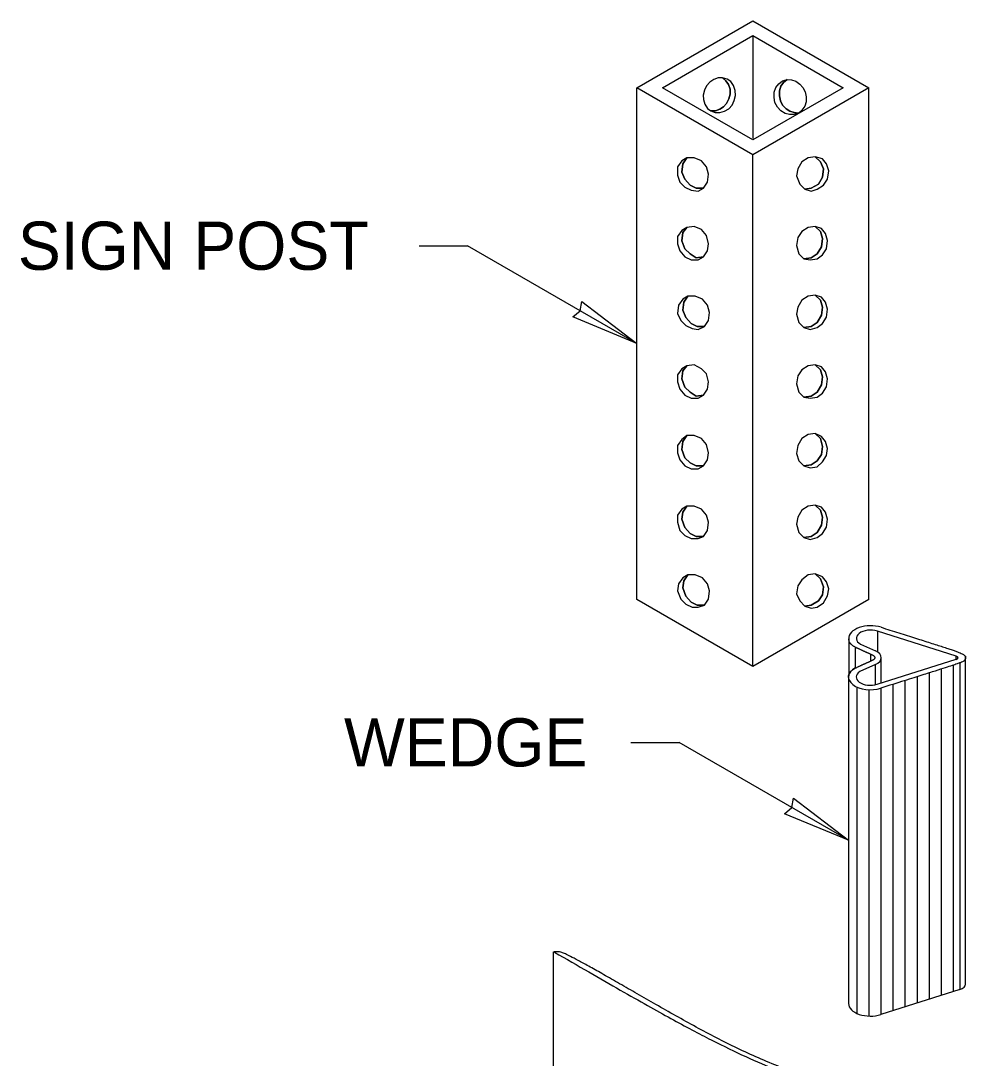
# Model space of a CAD drawing. Extents: x 99862 to 103680, y 99470 to 102076.
# Drawn here: x 101247.5 to 101566.5, y 100505.2 to 100849.7 of the extents above; entities that cross this region are included whole.
import ezdxf

# ---------------------------------------------------------------- set-up
doc = ezdxf.new("R2010")
doc.units = 0
for name, color, linetype in [('Level 15', 7, 'Continuous'), ('Level 2', 7, 'Continuous'), ('Level 20', 7, 'Continuous'), ('Level 4', 7, 'Continuous'), ('Level 8', 7, 'Continuous')]:
    doc.layers.add(name, color=color, linetype=linetype)

msp = doc.modelspace()

# ---------------------------------------------------------------- linework, layer by layer
at = {"layer": 'Level 15'}
for p, q in [((101379.81, 100775.01), (101395.81, 100775.01)), ((101452.1, 100742.51), (101395.81, 100775.01)), ((101450.1, 100610.06), (101466.1, 100610.06)), ((101522.39, 100577.56), (101466.1, 100610.06))]:
    msp.add_line(p, q, dxfattribs=at)
for points in [[(101452.1, 100742.51), (101430.84, 100751.34), (101433.24, 100753.39), (101433.82, 100756.51)], [(101522.39, 100577.56), (101501.13, 100586.39), (101503.54, 100588.45), (101504.11, 100591.56)]]:
    msp.add_lwpolyline(points, close=True, dxfattribs=at)
at = {"layer": 'Level 2'}
for p, q in [((101452.1, 100827.48), (101490.62, 100849.72)), ((101490.62, 100849.72), (101529.13, 100827.48)), ((101460.66, 100827.48), (101490.62, 100844.77)), ((101490.56, 100844.79), (101490.56, 100810.62)), ((101490.62, 100844.77), (101520.58, 100827.48)), ((101452.1, 100657.54), (101452.1, 100827.48)), ((101490.62, 100805.24), (101452.1, 100827.48)), ((101490.62, 100810.18), (101460.66, 100827.48)), ((101529.13, 100827.48), (101490.62, 100805.24)), ((101520.58, 100827.48), (101490.62, 100810.18)), ((101529.13, 100657.54), (101529.13, 100827.48)), ((101466.99, 100803.16), (101465.62, 100801.15)), ((101468.71, 100804.17), (101466.99, 100803.16)), ((101468.71, 100804.17), (101467.34, 100802.15)), ((101467.34, 100802.15), (101468.71, 100804.17)), ((101471.11, 100804.17), (101468.71, 100804.17)), ((101473.51, 100803.16), (101471.11, 100804.17)), ((101475.23, 100801.15), (101473.51, 100803.16)), ((101490.62, 100635.3), (101490.62, 100805.24)), ((101508.93, 100804.19), (101506.87, 100802.85)), ((101511.33, 100804.52), (101508.93, 100804.19)), ((101513.05, 100802.85), (101511.33, 100804.52)), ((101511.33, 100804.52), (101513.05, 100802.85)), ((101513.74, 100803.85), (101511.33, 100804.52)), ((101515.11, 100802.18), (101513.74, 100803.85)), ((101465.62, 100801.15), (101465.62, 100798.47)), ((101467.34, 100802.15), (101466.99, 100799.47)), ((101466.99, 100799.47), (101467.34, 100802.15)), ((101475.91, 100798.8), (101475.23, 100801.15)), ((101505.5, 100800.5), (101505.16, 100798.16)), ((101506.87, 100802.85), (101505.5, 100800.5)), ((101514.08, 100800.5), (101513.05, 100802.85)), ((101513.05, 100802.85), (101514.08, 100800.5)), ((101513.74, 100797.82), (101514.08, 100800.5)), ((101514.08, 100800.5), (101513.74, 100797.82)), ((101515.79, 100799.83), (101515.11, 100802.18)), ((101515.45, 100797.15), (101515.79, 100799.83)), ((101465.62, 100798.47), (101466.31, 100796.12)), ((101466.31, 100796.12), (101468.02, 100794.44)), ((101466.99, 100799.47), (101468.02, 100797.13)), ((101468.02, 100797.13), (101466.99, 100799.47)), ((101468.02, 100797.13), (101469.74, 100795.12)), ((101469.74, 100795.12), (101468.02, 100797.13)), ((101474.2, 100794.11), (101475.57, 100796.12)), ((101475.57, 100796.12), (101475.91, 100798.8)), ((101505.16, 100798.16), (101506.19, 100795.47)), ((101512.36, 100795.47), (101513.74, 100797.82)), ((101513.74, 100797.82), (101512.36, 100795.47)), ((101514.08, 100795.14), (101515.45, 100797.15)), ((101468.02, 100794.44), (101470.08, 100793.44)), ((101469.74, 100795.12), (101471.8, 100794.11)), ((101471.8, 100794.11), (101469.74, 100795.12)), ((101470.08, 100793.44), (101472.48, 100793.1)), ((101471.8, 100794.11), (101474.2, 100794.11)), ((101474.2, 100794.11), (101471.8, 100794.11)), ((101472.48, 100793.1), (101474.2, 100794.11)), ((101506.19, 100795.47), (101507.9, 100793.8)), ((101507.9, 100793.8), (101509.96, 100794.13)), ((101509.96, 100794.13), (101507.9, 100793.8)), ((101507.9, 100793.8), (101509.96, 100793.13)), ((101509.96, 100794.13), (101512.36, 100795.47)), ((101512.36, 100795.47), (101509.96, 100794.13)), ((101509.96, 100793.13), (101512.02, 100793.8)), ((101512.02, 100793.8), (101514.08, 100795.14)), ((101466.99, 100780.03), (101465.62, 100778.02)), ((101468.71, 100781.04), (101466.99, 100780.03)), ((101467.34, 100779.36), (101466.99, 100776.68)), ((101466.99, 100776.68), (101467.34, 100779.36)), ((101468.71, 100781.04), (101467.34, 100779.36)), ((101467.34, 100779.36), (101468.71, 100781.04)), ((101471.11, 100781.37), (101468.71, 100781.04)), ((101473.51, 100780.37), (101471.11, 100781.37)), ((101475.23, 100778.35), (101473.51, 100780.37)), ((101506.87, 100779.72), (101505.5, 100777.71)), ((101508.93, 100781.06), (101506.87, 100779.72)), ((101511.33, 100781.39), (101508.93, 100781.06)), ((101513.05, 100779.72), (101511.33, 100781.39)), ((101513.39, 100780.72), (101511.33, 100781.39)), ((101511.33, 100781.39), (101513.05, 100779.72)), ((101513.74, 100777.37), (101513.05, 100779.72)), ((101513.05, 100779.72), (101513.74, 100777.37)), ((101514.76, 100779.05), (101513.39, 100780.72)), ((101515.45, 100776.7), (101514.76, 100779.05)), ((101465.62, 100778.02), (101465.62, 100775.67)), ((101465.62, 100775.67), (101466.31, 100773.33)), ((101466.99, 100776.68), (101468.02, 100774)), ((101468.02, 100774), (101466.99, 100776.68)), ((101475.91, 100775.67), (101475.23, 100778.35)), ((101475.57, 100773.33), (101475.91, 100775.67)), ((101505.5, 100777.71), (101505.16, 100775.03)), ((101513.39, 100774.69), (101513.74, 100777.37)), ((101513.74, 100777.37), (101513.39, 100774.69)), ((101515.11, 100774.02), (101515.45, 100776.7)), ((101466.31, 100773.33), (101468.02, 100771.32)), ((101468.02, 100774), (101469.74, 100772.32)), ((101469.74, 100772.32), (101468.02, 100774)), ((101469.74, 100772.32), (101471.8, 100770.98)), ((101471.8, 100770.98), (101469.74, 100772.32)), ((101474.2, 100771.32), (101475.57, 100773.33)), ((101505.16, 100775.03), (101505.85, 100772.34)), ((101505.85, 100772.34), (101507.56, 100770.67)), ((101509.96, 100771), (101512.02, 100772.34)), ((101512.02, 100772.34), (101509.96, 100771)), ((101512.02, 100772.34), (101513.39, 100774.69)), ((101513.39, 100774.69), (101512.02, 100772.34)), ((101512.02, 100770.67), (101513.74, 100772.01)), ((101513.74, 100772.01), (101515.11, 100774.02)), ((101468.02, 100771.32), (101470.08, 100770.31)), ((101470.08, 100770.31), (101472.48, 100770.31)), ((101471.8, 100770.98), (101474.2, 100771.32)), ((101474.2, 100771.32), (101471.8, 100770.98)), ((101472.48, 100770.31), (101474.2, 100771.32)), ((101507.56, 100770.67), (101509.96, 100771)), ((101509.96, 100771), (101507.56, 100770.67)), ((101507.56, 100770.67), (101509.62, 100770.33)), ((101509.62, 100770.33), (101512.02, 100770.67)), ((101469.05, 100758.24), (101467.34, 100757.24)), ((101469.05, 100758.24), (101467.68, 100756.23)), ((101467.68, 100756.23), (101469.05, 100758.24)), ((101471.45, 100758.24), (101469.05, 100758.24)), ((101473.85, 100757.24), (101471.45, 100758.24)), ((101508.93, 100758.26), (101506.87, 100756.92)), ((101511.33, 100758.6), (101508.93, 100758.26)), ((101513.05, 100756.92), (101511.33, 100758.6)), ((101513.39, 100757.93), (101511.33, 100758.6)), ((101511.33, 100758.6), (101513.05, 100756.92)), ((101465.96, 100755.22), (101465.62, 100752.54)), ((101467.34, 100757.24), (101465.96, 100755.22)), ((101467.68, 100756.23), (101467.34, 100753.55)), ((101467.34, 100753.55), (101467.68, 100756.23)), ((101475.57, 100755.22), (101473.85, 100757.24)), ((101476.26, 100752.88), (101475.57, 100755.22)), ((101506.87, 100756.92), (101505.5, 100754.58)), ((101513.74, 100754.58), (101513.05, 100756.92)), ((101513.05, 100756.92), (101513.74, 100754.58)), ((101514.76, 100756.25), (101513.39, 100757.93)), ((101515.45, 100753.91), (101514.76, 100756.25)), ((101465.62, 100752.54), (101466.65, 100750.2)), ((101467.34, 100753.55), (101468.37, 100751.2)), ((101468.37, 100751.2), (101467.34, 100753.55)), ((101475.91, 100750.2), (101476.26, 100752.88)), ((101505.5, 100754.58), (101505.16, 100752.23)), ((101505.16, 100752.23), (101505.85, 100749.55)), ((101512.02, 100749.55), (101513.39, 100751.9)), ((101513.39, 100751.9), (101512.02, 100749.55)), ((101513.39, 100751.9), (101513.74, 100754.58)), ((101513.74, 100754.58), (101513.39, 100751.9)), ((101515.11, 100751.23), (101515.45, 100753.91)), ((101466.65, 100750.2), (101468.37, 100748.52)), ((101468.37, 100751.2), (101470.08, 100749.19)), ((101470.08, 100749.19), (101468.37, 100751.2)), ((101468.37, 100748.52), (101470.42, 100747.51)), ((101470.08, 100749.19), (101472.14, 100748.19)), ((101472.14, 100748.19), (101470.08, 100749.19)), ((101472.14, 100748.19), (101474.54, 100748.19)), ((101474.54, 100748.19), (101472.14, 100748.19)), ((101472.48, 100747.18), (101474.54, 100748.19)), ((101474.54, 100748.19), (101475.91, 100750.2)), ((101505.85, 100749.55), (101507.56, 100747.87)), ((101507.56, 100747.87), (101509.96, 100748.21)), ((101509.96, 100748.21), (101507.56, 100747.87)), ((101507.56, 100747.87), (101509.62, 100747.2)), ((101509.62, 100747.2), (101512.02, 100747.87)), ((101509.96, 100748.21), (101512.02, 100749.55)), ((101512.02, 100749.55), (101509.96, 100748.21)), ((101512.02, 100747.87), (101513.74, 100749.21)), ((101513.74, 100749.21), (101515.11, 100751.23)), ((101470.42, 100747.51), (101472.48, 100747.18)), ((101466.99, 100734.11), (101465.62, 100732.1)), ((101468.71, 100735.11), (101466.99, 100734.11)), ((101468.71, 100735.11), (101467.34, 100733.44)), ((101467.34, 100733.44), (101468.71, 100735.11)), ((101471.11, 100735.45), (101468.71, 100735.11)), ((101473.51, 100734.11), (101471.11, 100735.45)), ((101475.23, 100732.43), (101473.51, 100734.11)), ((101508.93, 100735.14), (101506.87, 100733.79)), ((101511.33, 100735.47), (101508.93, 100735.14)), ((101513.05, 100733.79), (101511.33, 100735.47)), ((101513.39, 100734.8), (101511.33, 100735.47)), ((101511.33, 100735.47), (101513.05, 100733.79)), ((101514.76, 100733.12), (101513.39, 100734.8)), ((101465.62, 100732.1), (101465.62, 100729.75)), ((101467.34, 100733.44), (101466.99, 100730.75)), ((101466.99, 100730.75), (101467.34, 100733.44)), ((101466.99, 100730.75), (101468.02, 100728.07)), ((101468.02, 100728.07), (101466.99, 100730.75)), ((101475.91, 100729.75), (101475.23, 100732.43)), ((101505.5, 100731.78), (101505.16, 100729.1)), ((101506.87, 100733.79), (101505.5, 100731.78)), ((101513.74, 100731.45), (101513.05, 100733.79)), ((101513.05, 100733.79), (101513.74, 100731.45)), ((101513.39, 100728.77), (101513.74, 100731.45)), ((101513.74, 100731.45), (101513.39, 100728.77)), ((101515.45, 100730.78), (101514.76, 100733.12)), ((101515.11, 100728.1), (101515.45, 100730.78)), ((101465.62, 100729.75), (101466.31, 100727.4)), ((101466.31, 100727.4), (101468.02, 100725.39)), ((101468.02, 100728.07), (101469.74, 100726.4)), ((101469.74, 100726.4), (101468.02, 100728.07)), ((101474.2, 100725.39), (101475.57, 100727.4)), ((101475.57, 100727.4), (101475.91, 100729.75)), ((101505.16, 100729.1), (101505.85, 100726.42)), ((101512.02, 100726.42), (101513.39, 100728.77)), ((101513.39, 100728.77), (101512.02, 100726.42)), ((101513.74, 100726.08), (101515.11, 100728.1)), ((101468.02, 100725.39), (101470.08, 100724.39)), ((101469.74, 100726.4), (101471.8, 100725.06)), ((101471.8, 100725.06), (101469.74, 100726.4)), ((101470.08, 100724.39), (101472.48, 100724.39)), ((101471.8, 100725.06), (101474.2, 100725.39)), ((101474.2, 100725.39), (101471.8, 100725.06)), ((101472.48, 100724.39), (101474.2, 100725.39)), ((101505.85, 100726.42), (101507.56, 100724.74)), ((101507.56, 100724.74), (101509.96, 100725.08)), ((101509.96, 100725.08), (101507.56, 100724.74)), ((101507.56, 100724.74), (101509.62, 100724.41)), ((101509.62, 100724.41), (101512.02, 100724.74)), ((101509.96, 100725.08), (101512.02, 100726.42)), ((101512.02, 100726.42), (101509.96, 100725.08)), ((101512.02, 100724.74), (101513.74, 100726.08)), ((101466.99, 100710.64), (101465.62, 100708.63)), ((101468.71, 100711.98), (101466.99, 100710.64)), ((101467.34, 100709.97), (101466.99, 100707.29)), ((101466.99, 100707.29), (101467.34, 100709.97)), ((101468.71, 100711.98), (101467.34, 100709.97)), ((101467.34, 100709.97), (101468.71, 100711.98)), ((101471.11, 100711.98), (101468.71, 100711.98)), ((101473.51, 100710.98), (101471.11, 100711.98)), ((101475.23, 100708.97), (101473.51, 100710.98)), ((101506.87, 100711), (101505.5, 100708.65)), ((101508.93, 100712.34), (101506.87, 100711)), ((101511.33, 100712.68), (101508.93, 100712.34)), ((101513.05, 100711), (101511.33, 100712.68)), ((101513.39, 100711.67), (101511.33, 100712.68)), ((101511.33, 100712.68), (101513.05, 100711)), ((101513.74, 100708.32), (101513.05, 100711)), ((101513.05, 100711), (101513.74, 100708.32)), ((101514.76, 100709.99), (101513.39, 100711.67)), ((101515.45, 100707.65), (101514.76, 100709.99)), ((101465.62, 100708.63), (101465.62, 100706.28)), ((101466.99, 100707.29), (101468.02, 100704.61)), ((101468.02, 100704.61), (101466.99, 100707.29)), ((101475.91, 100706.28), (101475.23, 100708.97)), ((101505.5, 100708.65), (101505.16, 100705.97)), ((101513.39, 100705.64), (101513.74, 100708.32)), ((101513.74, 100708.32), (101513.39, 100705.64)), ((101515.11, 100705.3), (101515.45, 100707.65)), ((101465.62, 100706.28), (101466.31, 100703.94)), ((101466.31, 100703.94), (101468.02, 100701.93)), ((101468.02, 100704.61), (101469.74, 100702.93)), ((101469.74, 100702.93), (101468.02, 100704.61)), ((101474.2, 100701.93), (101475.57, 100703.94)), ((101475.57, 100703.94), (101475.91, 100706.28)), ((101505.16, 100705.97), (101505.85, 100703.62)), ((101505.85, 100703.62), (101507.56, 100701.95)), ((101509.96, 100702.28), (101512.02, 100703.62)), ((101512.02, 100703.62), (101509.96, 100702.28)), ((101512.02, 100703.62), (101513.39, 100705.64)), ((101513.39, 100705.64), (101512.02, 100703.62)), ((101512.02, 100701.61), (101513.74, 100703.29)), ((101513.74, 100703.29), (101515.11, 100705.3)), ((101468.02, 100701.93), (101470.08, 100700.92)), ((101469.74, 100702.93), (101471.8, 100701.93)), ((101471.8, 100701.93), (101469.74, 100702.93)), ((101470.08, 100700.92), (101472.48, 100700.92)), ((101471.8, 100701.93), (101474.2, 100701.93)), ((101474.2, 100701.93), (101471.8, 100701.93)), ((101472.48, 100700.92), (101474.2, 100701.93)), ((101507.56, 100701.95), (101509.96, 100702.28)), ((101509.96, 100702.28), (101507.56, 100701.95)), ((101507.56, 100701.95), (101509.62, 100701.28)), ((101509.62, 100701.28), (101512.02, 100701.61)), ((101466.99, 100687.51), (101465.62, 100685.5)), ((101468.71, 100688.52), (101466.99, 100687.51)), ((101467.34, 100686.51), (101466.99, 100684.16)), ((101466.99, 100684.16), (101467.34, 100686.51)), ((101468.71, 100688.52), (101467.34, 100686.51)), ((101467.34, 100686.51), (101468.71, 100688.52)), ((101471.11, 100688.52), (101468.71, 100688.52)), ((101473.51, 100687.51), (101471.11, 100688.52)), ((101475.23, 100685.5), (101473.51, 100687.51)), ((101506.87, 100687.2), (101505.5, 100684.85)), ((101508.93, 100688.54), (101506.87, 100687.2)), ((101511.33, 100688.88), (101508.93, 100688.54)), ((101513.05, 100687.2), (101511.33, 100688.88)), ((101513.39, 100688.21), (101511.33, 100688.88)), ((101511.33, 100688.88), (101513.05, 100687.2)), ((101513.74, 100684.85), (101513.05, 100687.2)), ((101513.05, 100687.2), (101513.74, 100684.85)), ((101514.76, 100686.53), (101513.39, 100688.21)), ((101515.45, 100684.18), (101514.76, 100686.53)), ((101465.62, 100685.5), (101465.62, 100683.15)), ((101465.62, 100683.15), (101466.31, 100680.47)), ((101466.99, 100684.16), (101468.02, 100681.48)), ((101468.02, 100681.48), (101466.99, 100684.16)), ((101475.91, 100683.15), (101475.23, 100685.5)), ((101475.57, 100680.47), (101475.91, 100683.15)), ((101505.5, 100684.85), (101505.16, 100682.51)), ((101505.16, 100682.51), (101505.85, 100679.82)), ((101513.39, 100682.17), (101513.74, 100684.85)), ((101513.74, 100684.85), (101513.39, 100682.17)), ((101515.11, 100681.5), (101515.45, 100684.18)), ((101466.31, 100680.47), (101468.02, 100678.8)), ((101468.02, 100681.48), (101469.74, 100679.47)), ((101469.74, 100679.47), (101468.02, 100681.48)), ((101469.74, 100679.47), (101471.8, 100678.46)), ((101471.8, 100678.46), (101469.74, 100679.47)), ((101474.2, 100678.46), (101475.57, 100680.47)), ((101505.85, 100679.82), (101507.56, 100678.15)), ((101509.96, 100678.48), (101512.02, 100679.82)), ((101512.02, 100679.82), (101509.96, 100678.48)), ((101512.02, 100679.82), (101513.39, 100682.17)), ((101513.39, 100682.17), (101512.02, 100679.82)), ((101512.02, 100678.15), (101513.74, 100679.49)), ((101513.74, 100679.49), (101515.11, 100681.5)), ((101468.02, 100678.8), (101470.08, 100677.79)), ((101470.08, 100677.79), (101472.48, 100677.79)), ((101471.8, 100678.46), (101474.2, 100678.46)), ((101474.2, 100678.46), (101471.8, 100678.46)), ((101472.48, 100677.79), (101474.2, 100678.46)), ((101507.56, 100678.15), (101509.96, 100678.48)), ((101509.96, 100678.48), (101507.56, 100678.15)), ((101507.56, 100678.15), (101509.62, 100677.48)), ((101509.62, 100677.48), (101512.02, 100678.15)), ((101469.05, 100665.72), (101467.34, 100664.72)), ((101469.05, 100665.72), (101467.68, 100663.71)), ((101467.68, 100663.71), (101469.05, 100665.72)), ((101471.45, 100665.72), (101469.05, 100665.72)), ((101473.85, 100664.72), (101471.45, 100665.72)), ((101508.93, 100665.75), (101506.87, 100664.07)), ((101511.33, 100666.08), (101508.93, 100665.75)), ((101513.05, 100664.4), (101511.33, 100666.08)), ((101513.74, 100665.08), (101511.33, 100666.08)), ((101511.33, 100666.08), (101513.05, 100664.4)), ((101465.96, 100662.71), (101465.62, 100660.36)), ((101467.34, 100664.72), (101465.96, 100662.71)), ((101467.68, 100663.71), (101467.34, 100661.36)), ((101467.34, 100661.36), (101467.68, 100663.71)), ((101475.57, 100662.71), (101473.85, 100664.72)), ((101476.26, 100660.36), (101475.57, 100662.71)), ((101505.5, 100662.06), (101505.16, 100659.38)), ((101506.87, 100664.07), (101505.5, 100662.06)), ((101514.08, 100661.72), (101513.05, 100664.4)), ((101513.05, 100664.4), (101514.08, 100661.72)), ((101515.11, 100663.4), (101513.74, 100665.08)), ((101513.74, 100659.04), (101514.08, 100661.72)), ((101514.08, 100661.72), (101513.74, 100659.04)), ((101515.79, 100661.05), (101515.11, 100663.4)), ((101465.62, 100660.36), (101466.65, 100657.68)), ((101467.34, 100661.36), (101468.37, 100658.68)), ((101468.37, 100658.68), (101467.34, 100661.36)), ((101468.37, 100658.68), (101470.08, 100656.67)), ((101470.08, 100656.67), (101468.37, 100658.68)), ((101475.91, 100657.68), (101476.26, 100660.36)), ((101505.16, 100659.38), (101506.19, 100657.03)), ((101512.36, 100657.03), (101513.74, 100659.04)), ((101513.74, 100659.04), (101512.36, 100657.03)), ((101514.08, 100656.36), (101515.45, 100658.71)), ((101515.45, 100658.71), (101515.79, 100661.05)), ((101490.62, 100635.3), (101452.1, 100657.54)), ((101466.65, 100657.68), (101468.37, 100656)), ((101468.37, 100656), (101470.42, 100655)), ((101470.08, 100656.67), (101472.14, 100655.67)), ((101472.14, 100655.67), (101470.08, 100656.67)), ((101470.42, 100655), (101472.48, 100655)), ((101472.14, 100655.67), (101474.54, 100655.67)), ((101474.54, 100655.67), (101472.14, 100655.67)), ((101472.48, 100655), (101474.54, 100655.67)), ((101474.54, 100655.67), (101475.91, 100657.68)), ((101529.13, 100657.54), (101490.62, 100635.3)), ((101506.19, 100657.03), (101507.9, 100655.35)), ((101507.9, 100655.35), (101509.96, 100655.69)), ((101509.96, 100655.69), (101507.9, 100655.35)), ((101507.9, 100655.35), (101509.96, 100654.68)), ((101509.96, 100655.69), (101512.36, 100657.03)), ((101512.36, 100657.03), (101509.96, 100655.69)), ((101509.96, 100654.68), (101512.02, 100655.02)), ((101512.02, 100655.02), (101514.08, 100656.36))]:
    msp.add_line(p, q, dxfattribs=at)
for points in [[(101476.65, 100819.77), (101478.21, 100819.77), (101479.63, 100820.33), (101480.91, 100821.16), (101481.9, 100822.27), (101482.61, 100823.8), (101483.04, 100825.32), (101483.04, 100826.99), (101482.47, 100828.52), (101481.62, 100829.76), (101480.48, 100830.74), (101479.06, 100830.74), (101477.64, 100830.18), (101476.36, 100829.35), (101475.23, 100828.1), (101474.52, 100826.71), (101474.09, 100825.05), (101474.23, 100823.52), (101474.66, 100821.99), (101475.51, 100820.61), (101476.65, 100819.77)], [(101476.65, 100819.77), (101478.07, 100819.22), (101479.63, 100819.22), (101481.19, 100819.64), (101482.61, 100820.47), (101483.75, 100821.72), (101484.46, 100823.24), (101484.88, 100824.91), (101484.74, 100826.57), (101484.17, 100828.24), (101483.32, 100829.49), (101482.04, 100830.32), (101480.48, 100830.74), (101481.62, 100829.76), (101482.47, 100828.52), (101483.04, 100826.99), (101483.04, 100825.32), (101482.61, 100823.8), (101481.9, 100822.27), (101480.91, 100821.16), (101479.63, 100820.33), (101478.21, 100819.77), (101476.65, 100819.77)], [(101505.76, 100819.08), (101504.34, 100818.53), (101502.77, 100818.53), (101501.35, 100818.94), (101499.93, 100819.77), (101498.8, 100821.02), (101497.95, 100822.55), (101497.66, 100824.21), (101497.66, 100826.02), (101498.23, 100827.54), (101499.22, 100828.79), (101500.5, 100829.76), (101502.06, 100830.18), (101500.79, 100829.21), (101499.93, 100827.96), (101499.51, 100826.43), (101499.51, 100824.77), (101499.79, 100823.1), (101500.5, 100821.72), (101501.64, 100820.47), (101502.92, 100819.64), (101504.34, 100819.22), (101505.76, 100819.08)], [(101505.76, 100819.08), (101504.34, 100819.22), (101502.92, 100819.64), (101501.64, 100820.47), (101500.5, 100821.72), (101499.79, 100823.1), (101499.51, 100824.77), (101499.51, 100826.43), (101499.93, 100827.96), (101500.79, 100829.21), (101502.06, 100830.18), (101503.48, 100830.04), (101504.9, 100829.63), (101506.18, 100828.65), (101507.18, 100827.54), (101508.03, 100826.16), (101508.31, 100824.49), (101508.31, 100822.83), (101507.89, 100821.3), (101506.89, 100820.05), (101505.76, 100819.08)]]:
    msp.add_lwpolyline(points, dxfattribs=at)
at = {"layer": 'Level 4'}
for p, q in [((101531.96, 100647.01), (101531.96, 100640.13)), ((101524.56, 100641.66), (101524.56, 100634.75)), ((101529.78, 100637.1), (101529.78, 100639.3)), ((101558.17, 100637.65), (101558.17, 100638.75)), ((101531.34, 100629.22), (101531.34, 100635.95)), ((101553.13, 100634.39), (101553.13, 100525.99)), ((101557.13, 100635.65), (101557.13, 100527.25)), ((101559.39, 100636.36), (101559.39, 100527.96)), ((101545.13, 100631.87), (101545.13, 100523.46)), ((101549.13, 100633.13), (101549.13, 100524.73)), ((101525.13, 100628.48), (101525.13, 100520.08)), ((101529.13, 100627.58), (101529.13, 100519.18)), ((101533.13, 100628.08), (101533.13, 100519.68)), ((101537.13, 100629.34), (101537.13, 100520.94)), ((101541.13, 100630.61), (101541.13, 100522.2)), ((101424.44, 100415.97), (101424.44, 100540.53))]:
    msp.add_line(p, q, dxfattribs=at)
for points in [[(101566.45, 100478.45), (101566.22, 100480.34), (101563.34, 100481.25), (101527.44, 100492.57), (101491.54, 100503.88), (101459.78, 100522.22), (101428.01, 100540.56), (101426.23, 100540.56), (101424.45, 100540.56), (101424.48, 100540.54), (101424.51, 100540.53)], [(101424.73, 100540.4), (101457.37, 100521.55), (101490.02, 100502.71), (101526.07, 100491.34), (101562.13, 100479.97), (101563.94, 100479.4), (101563.94, 100478.21), (101563.94, 100477.02), (101562.13, 100476.45), (101526.07, 100465.08), (101490.02, 100453.72), (101457.4, 100434.88), (101424.77, 100416.05), (101424.61, 100415.95), (101424.45, 100415.86), (101426.23, 100415.86), (101428.01, 100415.86), (101459.78, 100434.2), (101491.54, 100452.54), (101527.44, 100463.85), (101563.34, 100475.17), (101566.34, 100476.12), (101566.46, 100478.09)]]:
    msp.add_open_spline(points, degree=4, dxfattribs=at)
at = {"layer": 'Level 8'}
for p, q in [((101522.43, 100644.62), (101522.43, 100644.51)), ((101522.43, 100644.51), (101522.43, 100632.22)), ((101558.17, 100638.75), (101531.96, 100647.01)), ((101526.36, 100642.7), (101531.34, 100640.46)), ((101531.92, 100629.37), (101558.17, 100637.65)), ((101533.25, 100629.79), (101533.25, 100638.2)), ((101561.28, 100529.8), (101561.28, 100638.49)), ((101531.34, 100635.95), (101526.09, 100633.57)), ((101522.39, 100631.76), (101522.39, 100523.36)), ((101559.39, 100527.96), (101533.13, 100519.68))]:
    msp.add_line(p, q, dxfattribs=at)
for centre, major_axis, start_param, end_param in [((101529.7, 100644.62), (7.26, 0), 1.071036, 3.168526), ((101529.7, 100644.62), (-4.72, 0), 4.212629, 7.06792), ((101528.29, 100638.2), (-4.96, 0), 2.234021, 4.049164), ((101557.65, 100638.2), (-1.09, 0), 2.070557, 4.212629), ((101529.65, 100631.76), (7.26, 0), 2.355531, 5.212149), ((101529.65, 100631.76), (-4.72, 0), 5.562042, 8.353742), ((101557.65, 100529.8), (3.63, 0), 5.212149, 6.283185), ((101529.65, 100523.36), (7.26, 0), 3.141593, 5.212149)]:
    msp.add_ellipse(centre, major_axis=major_axis, ratio=0.57735, start_param=start_param, end_param=end_param, dxfattribs=at)
for points in [[(101533.18, 100648.3), (101546.28, 100644.17), (101559.39, 100640.04), (101560.99, 100639.53), (101561.24, 100638.49)], [(101522.39, 100631.64), (101522.3, 100633.45), (101524.52, 100634.73), (101527.15, 100635.92), (101529.78, 100637.1), (101532.22, 100638.2), (101529.78, 100639.3), (101527.17, 100640.48), (101524.56, 100641.66), (101522.51, 100642.84), (101522.44, 100644.51)], [(101561.24, 100638.49), (101561.28, 100638.35), (101561.28, 100638.2), (101561.28, 100636.96), (101559.39, 100636.36), (101546.26, 100632.22), (101533.13, 100628.08)]]:
    msp.add_open_spline(points, degree=4, dxfattribs=at)

# ---------------------------------------------------------------- texts
at = {"layer": 'Level 20'}
for s, p in [('SIGN POST', (101246.52, 100767.01)), ('WEDGE', (101354.83, 100602.07))]:
    msp.add_text(s, height=16, dxfattribs=at).set_placement(p)

doc.saveas('drawing.dxf')
